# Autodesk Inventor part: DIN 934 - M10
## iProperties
Comments: To add or edit properties for Autodesk Inventor files, use iProperties.
Created: 2003-09
Part Number: DIN 934 - M10
Vendor: Autodesk Inc.
Document SubType Name: Modeling
Designer: lamberj
Material: Default
Description: Hex Nut
Standard: DIN 934
Manufacturer: Standard
Standards Organization: Custom
Alert: To add or edit properties for Autodesk Inventor files, use iProperties.
Control State: 0
Master: False
Checked Out: False
Shininess: 64.0
Length Units: 11269
Angle Units: 11279
Time Units: 11290
Mass Units: 11283
Length Display Precision: 3
Angle Display Precision: 2
Compacted: True
EGR: 1
Classification: un/spsc 31161727
Density: 0.0
Volumn: 0.0
Area: 0.0
PropertySet Name: Model Information
Author: lamberj
Revision Number: 5
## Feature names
1. Body [Extrusion]
2. Chamfer1 [Revolution]
3. Thread [Hole]
4. Chamfer2
5. Chamfer3
